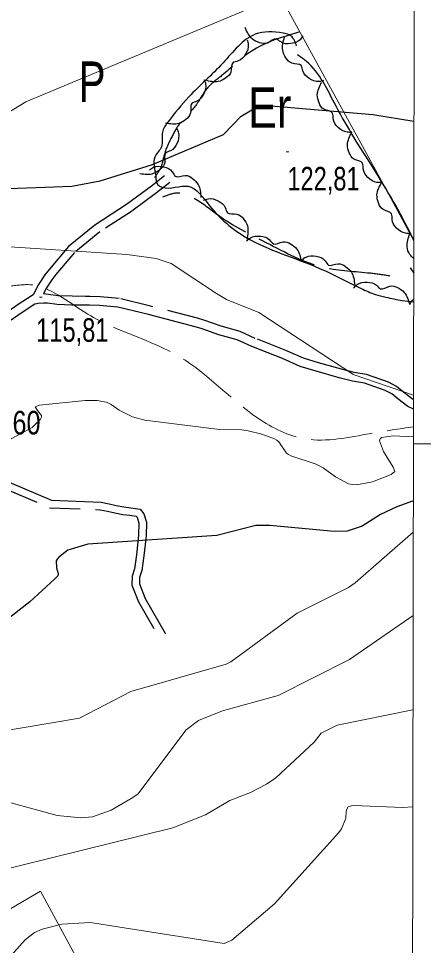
# Model space of a CAD drawing. Extents: x 483843 to 488449, y 4381269 to 4384483.
# Drawn here: x 487529.4 to 487679.8, y 4382813.6 to 4383158 of the extents above; entities that cross this region are included whole.
import ezdxf
from ezdxf.enums import TextEntityAlignment as Align

# ---------------------------------------------------------------- set-up
doc = ezdxf.new("R2010")
doc.units = 0
doc.header["$LTSCALE"] = 3.8
doc.linetypes.add('LONG_DASHED', pattern=[7.5, 6, -1.5])
doc.linetypes.add('MEDIUM_DASHED', pattern=[4.5, 3, -1.5])
for name, color, linetype, lineweight in [('1', 7, 'Continuous', 13), ('15', 7, 'LONG_DASHED', 13), ('25', 7, 'LONG_DASHED', 25), ('27', 7, 'Continuous', 25), ('38', 7, 'Continuous', 25), ('51', 7, 'Continuous', 13), ('7', 7, 'Continuous', 13), ('8', 7, 'Continuous', 25), ('9', 7, 'Continuous', 13)]:
    doc.layers.add(name, color=color, linetype=linetype, lineweight=lineweight)
doc.layers.add('31', color=7, linetype='Continuous')

msp = doc.modelspace()

# ---------------------------------------------------------------- linework, layer by layer
at = {"layer": '1'}
msp.add_line((487676.1, 4383000), (487726.38, 4383000), dxfattribs=at)
msp.add_lwpolyline([(484100.5, 4384135.8), (487678, 4384129), (487674.1, 4381816.7), (484095.6, 4381823.6)], close=True, dxfattribs=at)
at = {"layer": '15'}
msp.add_spline([(487221.06, 4383017.02), (487234.43, 4383028.96), (487242.08, 4383044.65), (487243.71, 4383068.31), (487253.91, 4383088.99), (487269.42, 4383103.3), (487286.4, 4383111.29), (487293.87, 4383114.85), (487302.47, 4383114.04), (487309.94, 4383111.83), (487319.96, 4383105.84), (487328.44, 4383096.64), (487337.84, 4383078.44), (487333.71, 4383063.44), (487338.23, 4383039.99), (487350.49, 4383012.9), (487363.48, 4382994.2), (487374.59, 4382991.03), (487396.25, 4382990.86), (487426.03, 4383002.55), (487454.21, 4383017.72), (487477.23, 4383038.65), (487493.13, 4383054.75), (487525.49, 4383058.46), (487532.91, 4383059.1), (487555.16, 4383048.13), (487589.24, 4383032.33), (487618.28, 4383009.56), (487636, 4383001.8), (487660.23, 4383003.83), (487676.11, 4383006.29)], degree=3, dxfattribs=at)
at = {"layer": '25'}
for points in [[(487633.92, 4383152.99), (487615.77, 4383145.74), (487604.84, 4383136.74), (487599.44, 4383132.01), (487594.92, 4383125.25), (487589.73, 4383119.62), (487586.43, 4383114.19), (487583.56, 4383107.55), (487582.21, 4383102.62), (487579.75, 4383098.45), (487578.05, 4383094.62)], [(487667.52, 4383062.29), (487660.14, 4383063.31), (487643.13, 4383065.35), (487621.36, 4383074.67), (487603.64, 4383084.75), (487594.65, 4383091.11), (487588.23, 4383093.08), (487582.88, 4383091.58)]]:
    msp.add_spline(points, degree=3, dxfattribs=at)
at = {"layer": '27'}
for points in [[(487635.08, 4383151.47), (487633.97, 4383150.08), (487630.47, 4383148.63), (487626.83, 4383149.26), (487625.11, 4383150.39), (487621.9, 4383148.86), (487618.92, 4383148.99), (487616.23, 4383150.37), (487613.6, 4383154.57)], [(487632.68, 4383147.82), (487630.64, 4383151.45), (487627.65, 4383152.54), (487617.36, 4383152.09), (487605.36, 4383141.46), (487592.64, 4383128.88), (487584.86, 4383119.47), (487582.85, 4383115.74), (487582.47, 4383110.35), (487580.02, 4383106.48), (487579.75, 4383103.26), (487580.36, 4383099.27), (487581.07, 4383096.33), (487582.63, 4383095.34), (487592.39, 4383095.65), (487600.39, 4383088.4), (487615.59, 4383075.73), (487642.67, 4383064.54), (487648.63, 4383061.67), (487656.68, 4383057.73), (487661.98, 4383055.48), (487665.86, 4383054.45), (487671.92, 4383053.24), (487676.18, 4383052.68)], [(487614.33, 4383150.05), (487614.74, 4383148.33), (487613.73, 4383144.67), (487610.99, 4383142.2), (487609.04, 4383141.54), (487608.27, 4383138.07), (487606.33, 4383135.8), (487603.59, 4383134.53), (487598.66, 4383135.05)], [(487642.71, 4383134.92), (487640.97, 4383134.57), (487637.35, 4383135.69), (487634.96, 4383138.51), (487634.37, 4383140.47), (487630.92, 4383141.36), (487628.71, 4383143.36), (487627.53, 4383146.15), (487628.21, 4383151.06)], [(487676.22, 4383075.69), (487675.57, 4383077.05), (487661, 4383102.69), (487647.37, 4383125.4), (487636.28, 4383142.07), (487633.09, 4383144.44)], [(487598.33, 4383135.35), (487598.89, 4383133.66), (487598.19, 4383129.93), (487595.67, 4383127.24), (487593.79, 4383126.41), (487593.31, 4383122.89), (487591.57, 4383120.46), (487588.95, 4383118.96), (487583.99, 4383119.06)], [(487653.21, 4383115.74), (487651.44, 4383115.72), (487648.09, 4383117.5), (487646.27, 4383120.72), (487646.06, 4383122.76), (487642.84, 4383124.27), (487641.05, 4383126.66), (487640.4, 4383129.61), (487641.99, 4383134.31)], [(487588.24, 4383117.05), (487588.85, 4383115.39), (487588.29, 4383111.64), (487585.87, 4383108.85), (487584.02, 4383107.96), (487583.68, 4383104.42), (487582.03, 4383101.93), (487579.46, 4383100.34), (487574.5, 4383100.25)], [(487664.33, 4383097.1), (487662.55, 4383097.09), (487659.22, 4383098.9), (487657.42, 4383102.13), (487657.22, 4383104.17), (487654.01, 4383105.7), (487652.23, 4383108.1), (487651.61, 4383111.06), (487653.23, 4383115.75)], [(487577.99, 4383101.77), (487579.5, 4383102.69), (487583.29, 4383102.87), (487586.49, 4383101.03), (487587.72, 4383099.37), (487591.26, 4383099.71), (487594.02, 4383098.57), (487596.08, 4383096.35), (487597.1, 4383091.5)], [(487674.94, 4383078.17), (487673.16, 4383078.21), (487669.87, 4383080.09), (487668.16, 4383083.36), (487668, 4383085.41), (487664.83, 4383087.02), (487663.12, 4383089.46), (487662.57, 4383092.44), (487664.3, 4383097.08)], [(487598.1, 4383090.45), (487599.79, 4383090.99), (487603.52, 4383090.26), (487606.19, 4383087.72), (487607, 4383085.83), (487610.52, 4383085.32), (487612.93, 4383083.56), (487614.41, 4383080.92), (487614.26, 4383075.97)], [(487614.14, 4383075.35), (487615.52, 4383076.46), (487619.26, 4383077.12), (487622.67, 4383075.71), (487624.1, 4383074.24), (487627.57, 4383075.03), (487630.45, 4383074.26), (487632.78, 4383072.33), (487634.43, 4383067.65)], [(487676.21, 4383068.85), (487674.77, 4383070.36), (487673.77, 4383073.21), (487674.78, 4383078.07)], [(487634.73, 4383068.35), (487636.2, 4383069.34), (487639.98, 4383069.68), (487643.26, 4383067.99), (487644.56, 4383066.4), (487648.08, 4383066.89), (487650.89, 4383065.88), (487653.04, 4383063.75), (487654.28, 4383058.95)], [(487653.88, 4383057.89), (487655.18, 4383059.1), (487658.86, 4383060.03), (487662.36, 4383058.87), (487663.9, 4383057.51), (487667.3, 4383058.55), (487670.23, 4383057.99), (487672.69, 4383056.24), (487674.68, 4383051.69)], [(487674.87, 4383051.74), (487675.72, 4383053.3), (487676.19, 4383053.6)]]:
    msp.add_spline(points, degree=3, dxfattribs=at)
at = {"layer": '38', "linetype": 'MEDIUM_DASHED'}
msp.add_line((487674.94, 4383065.34), (487676.2, 4383063.32), dxfattribs=at)
at = {"layer": '38'}
for points in [[(487583.66, 4383099.53), (487578.74, 4383095.71), (487569.51, 4383088.89), (487557.68, 4383081.24), (487547.93, 4383073.26), (487540.84, 4383064.88), (487539.11, 4383062.75), (487536.84, 4383059.1), (487534.82, 4383055.27)], [(487676.12, 4383012.81), (487673.98, 4383013.78), (487670.37, 4383016.68), (487668.07, 4383018.56), (487665.57, 4383019.82), (487657.87, 4383022.51), (487653.42, 4383023.31), (487648.52, 4383024.53), (487639.93, 4383026.92), (487634.07, 4383028.71), (487627.48, 4383031.62), (487616.05, 4383036.14), (487610.67, 4383038.64), (487603.75, 4383040.51), (487597.26, 4383042.86), (487595.05, 4383043.46), (487577.67, 4383047.98), (487566.23, 4383050.72), (487559.52, 4383051.31), (487555.78, 4383051.44), (487554.24, 4383051.47), (487549.18, 4383051.54), (487543.79, 4383051.77), (487540.1, 4383052.2), (487538.69, 4383052.28), (487536.67, 4383052.05), (487535.45, 4383051.82), (487530.71, 4383048.81), (487525.86, 4383045.44)], [(487500.65, 4382999.8), (487505.03, 4382995.13), (487512.66, 4382993.67), (487519.2, 4382989.23), (487521.05, 4382987.86), (487526.8, 4382985.37), (487541.57, 4382979), (487560.02, 4382978.28), (487563.02, 4382977.71), (487565.71, 4382977.08), (487568.55, 4382976.51), (487571.1, 4382976.25), (487574.61, 4382975.67), (487575.93, 4382974.01), (487576.93, 4382970.86), (487576.78, 4382965.83), (487575.92, 4382958.34), (487575.17, 4382952.95), (487574.38, 4382950.33), (487574.27, 4382947.93), (487576.46, 4382942.49), (487584, 4382929.33)]]:
    msp.add_lwpolyline(points, dxfattribs=at)
at = {"layer": '38', "linetype": 'MEDIUM_DASHED'}
for points in [[(487585.6, 4383097.04), (487580.65, 4383093.19), (487571.31, 4383086.3), (487559.55, 4383078.69), (487550.15, 4383071), (487543.27, 4383062.87), (487541.69, 4383060.92), (487539.58, 4383057.52), (487538.6, 4383055.66)], [(487534.82, 4383055.27), (487528.9, 4383051.52), (487523.77, 4383047.95), (487518.2, 4383042.39), (487512.09, 4383032.81), (487504.29, 4383020.02), (487502.2, 4383013.48)], [(487676.12, 4383016.39), (487675.7, 4383016.58), (487672.42, 4383019.21), (487669.85, 4383021.31), (487666.85, 4383022.83), (487658.7, 4383025.67), (487654.1, 4383026.49), (487649.35, 4383027.68), (487640.85, 4383030.05), (487635.21, 4383031.77), (487628.74, 4383034.63), (487617.34, 4383039.14), (487611.79, 4383041.71), (487604.73, 4383043.62), (487598.24, 4383045.97), (487595.89, 4383046.61), (487578.46, 4383051.14), (487566.75, 4383053.94), (487559.72, 4383054.57), (487555.87, 4383054.7), (487554.29, 4383054.73), (487549.27, 4383054.8), (487544.05, 4383055.01), (487538.6, 4383055.66)], [(487499.29, 4382997.17), (487503.62, 4382992.57), (487511.57, 4382991.05), (487517.59, 4382986.95), (487519.65, 4382985.43), (487525.7, 4382982.81), (487540.94, 4382976.24), (487559.7, 4382975.51), (487562.44, 4382974.99), (487565.11, 4382974.36), (487568.13, 4382973.75), (487570.73, 4382973.49), (487573.09, 4382973.1), (487573.42, 4382972.68), (487574.13, 4382970.46), (487574, 4382966.03), (487573.16, 4382958.69), (487572.44, 4382953.55), (487571.62, 4382950.81), (487571.46, 4382947.45), (487573.94, 4382941.28), (487581.58, 4382927.95)]]:
    msp.add_lwpolyline(points, dxfattribs=at)
at = {"layer": '51'}
for points in [[(487586.9, 4383238.73), (487664.23, 4383097.69), (487676.22, 4383075.41)], [(487537.56, 4382833.81), (487285.63, 4382686.27), (486981.61, 4382494.14), (487135.5, 4382250.96)], [(487537.56, 4382833.81), (487602.08, 4382714.56), (487669.71, 4382586.44), (487435.47, 4382436.11), (487444.74, 4382412.08), (487333, 4382339.77), (487364.19, 4382236.17), (487545.79, 4382353.89)]]:
    msp.add_lwpolyline(points, dxfattribs=at)
at = {"layer": '7'}
for p, q in [((487628.77, 4383108.47), (487629.77, 4383108.47)), ((487537.13, 4383054.48), (487538.13, 4383054.48))]:
    msp.add_line(p, q, dxfattribs=at)
at = {"layer": '8'}
for points in [[(487481.87, 4383093.17), (487549.16, 4383095.74), (487559.77, 4383097.67), (487579.14, 4383103.71), (487605.55, 4383114.84), (487612.13, 4383121.75), (487617.6, 4383124.93), (487619.64, 4383125.38), (487621.92, 4383125.64), (487660.97, 4383122.27), (487676.3, 4383119.87)], [(487676.06, 4382978.7), (487675.78, 4382978.66), (487669.88, 4382976.59), (487663.89, 4382973.7), (487657, 4382969.34), (487651.47, 4382967.54), (487646.67, 4382967.36), (487622.72, 4382969.69), (487617.55, 4382969.58), (487603.12, 4382965.95), (487555.15, 4382962.73), (487547.64, 4382960.51), (487544.31, 4382957.87), (487543.78, 4382957.16), (487543.42, 4382956.45), (487543.5, 4382953.97), (487544.1, 4382951.84), (487544.07, 4382951.36), (487543.95, 4382950.92), (487542.78, 4382949.72), (487533.57, 4382941.24), (487513.06, 4382925.28)]]:
    msp.add_lwpolyline(points, dxfattribs=at)
at = {"layer": '9'}
for points in [[(487426.5, 4383165.84), (487452.22, 4383156.92), (487457.72, 4383152.96), (487494.95, 4383116.66), (487495.54, 4383116.3), (487496.22, 4383115.97), (487499.46, 4383115.01), (487506.8, 4383113.92), (487508.89, 4383114.08), (487510.21, 4383114.39), (487512.86, 4383115.34), (487532.13, 4383127), (487676.41, 4383187.33)], [(487676.13, 4383018.03), (487653.68, 4383025.76), (487653.63, 4383025.79), (487653.54, 4383025.86), (487618.65, 4383048.74), (487606.67, 4383053.59), (487602.99, 4383055.76), (487586.08, 4383066.94), (487580.53, 4383068.87), (487569.6, 4383070.36), (487520.33, 4383073.53)], [(487537.95, 4383010.5), (487536.4, 4383012.35), (487535.61, 4383013.67), (487536.19, 4383013.99), (487537.11, 4383014.29), (487554.13, 4383016.04), (487558.65, 4383016.06), (487562.08, 4383015.41), (487563.85, 4383014.63), (487566.82, 4383012.47), (487571.78, 4383010.01), (487576.35, 4383008.81), (487604.05, 4383005.24), (487612.39, 4383005.21), (487614.74, 4383004.86), (487619.84, 4383003.6), (487624.47, 4383001.83), (487625.39, 4383001.29), (487626.15, 4383000.73), (487628.93, 4382996.5), (487629.65, 4382996), (487630.5, 4382995.54), (487639.91, 4382992.44), (487642.59, 4382991.06), (487647.17, 4382987.77), (487651.96, 4382985.15), (487653.42, 4382984.85), (487654.94, 4382984.73), (487660.92, 4382985.81), (487667.84, 4382988.62), (487669.15, 4382989.68), (487668.56, 4382991.28), (487664.94, 4382997.08), (487663.45, 4383001.04), (487663.7, 4383001.77), (487664.24, 4383002.33), (487668.62, 4383003), (487676.1, 4383002.54)], [(487525.09, 4383001), (487534.48, 4383006.01), (487537.54, 4383009.13), (487537.86, 4383009.84), (487537.95, 4383010.5)], [(487676.04, 4382967.1), (487654.4, 4382948.31), (487651.93, 4382946.58), (487632.96, 4382937.06), (487608.32, 4382918.94), (487606.54, 4382918.1), (487571.1, 4382907.97), (487551.99, 4382898.01), (487510.74, 4382891.15)], [(487675.99, 4382936.24), (487652.37, 4382919.9), (487625.86, 4382906.54), (487605.22, 4382900.82), (487596.24, 4382897.22), (487591.72, 4382893.78), (487573.7, 4382869.87), (487571.27, 4382868.17), (487563.75, 4382863.84), (487556.85, 4382861.44), (487552.51, 4382861.01), (487543.74, 4382861.86), (487520.55, 4382868.24)], [(487518.41, 4382840.51), (487586.72, 4382857.31), (487598.84, 4382862.21), (487607.89, 4382867.43), (487615.56, 4382870.43), (487621.52, 4382873.51), (487624.94, 4382875.85), (487639.21, 4382889.15), (487641.88, 4382892.52), (487647.72, 4382895.46), (487675.93, 4382901.14)], [(487675.87, 4382865.11), (487672, 4382864.89), (487654.08, 4382865.61), (487653.07, 4382865.48), (487652.59, 4382865.37), (487651.87, 4382865.1), (487651.33, 4382864.27), (487651.13, 4382863.35), (487650.93, 4382860.87), (487649.32, 4382856.95), (487648.33, 4382855.54), (487624.51, 4382829.08), (487608.69, 4382815.63), (487605.74, 4382814.3), (487555.98, 4382822.12), (487545.5, 4382821.56), (487538.2, 4382819.68), (487535.25, 4382818.42), (487531.89, 4382815.73), (487506.5, 4382787.54)]]:
    msp.add_lwpolyline(points, dxfattribs=at)

# ---------------------------------------------------------------- texts
at = {"layer": '31'}
for s, width, p in [('P', 0.75, (487556.69, 4383127)), ('Er', 0.8, (487622.68, 4383117.39))]:
    msp.add_text(s, height=15, dxfattribs=dict(at, width=width)).set_placement(p, align=Align.CENTER)
at = {"layer": '7'}
for s, width, p in [('122,81', 0.75, (487629.27, 4383094.1)), ('115,81', 0.75, (487535.95, 4383037.88)), ('117,60', 0.8, (487508.92, 4383003.45))]:
    msp.add_text(s, height=8.75, dxfattribs=dict(at, width=width)).set_placement(p)

doc.saveas('drawing.dxf')
